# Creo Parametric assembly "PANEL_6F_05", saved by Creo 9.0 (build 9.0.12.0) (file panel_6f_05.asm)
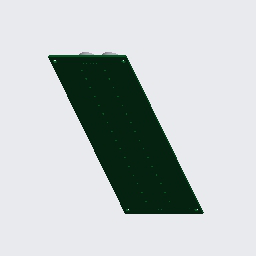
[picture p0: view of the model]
Units: millimeter Newton Second (mmNs); MM, TONNE, SECS

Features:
  1. coordinate system "PANEL_6F_05"
  2. imported feature "Import Feature id 4"
  3. component "PCB_6F"
  4. component "TX_6F_T1"
  5. component "TX_6F_T1"
  6. component "TX_6F_T1"
  7. component "TX_6F_T1"
  8. component "TX_6F_T1"
  9. component "TX_6F_T1"
  10. component "TX_6F_T1"
  11. component "TX_6F_T1"
  12. component "TX_6F_T1"
  13. component "TX_6F_T1"
  14. component "TX_6F_T1"
  15. component "TX_6F_T1"
  16. component "TX_6F_T1"
  17. component "TX_6F_T1"
  18. component "TX_6F_T1"
  19. component "TX_6F_T1"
